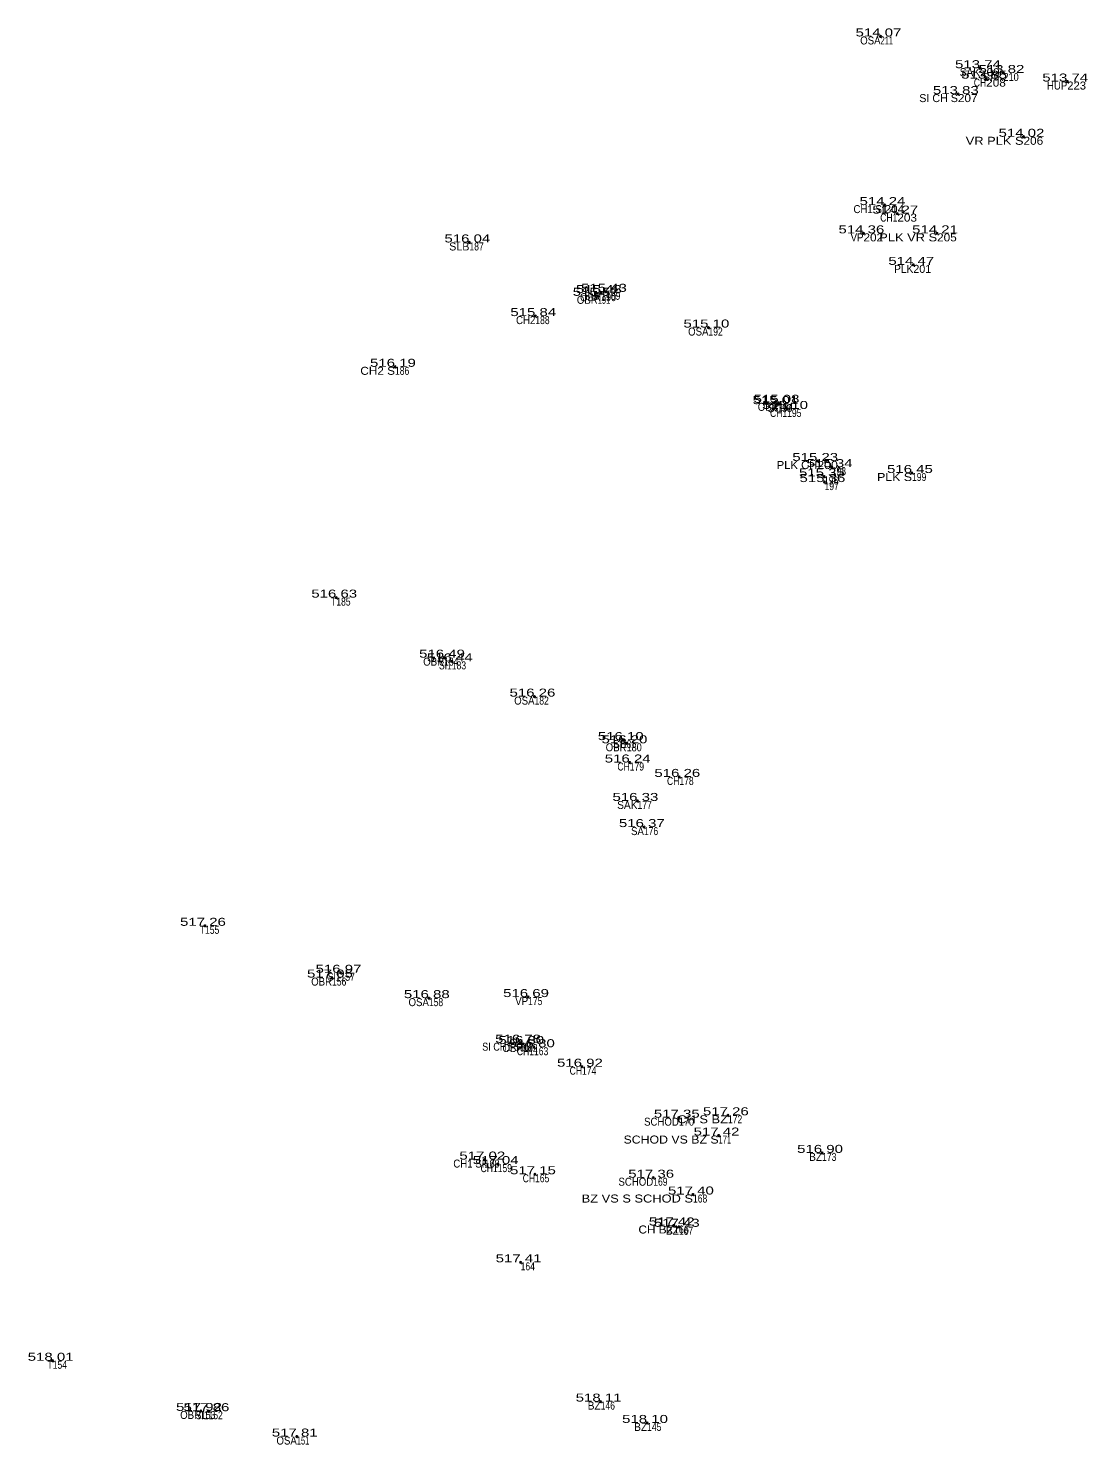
# Model space of a CAD drawing. Extents: x -643086 to -639283, y -1131805 to -1123269.
# Drawn here: x -641480.8 to -641441.1, y -1126139.9 to -1126086.8 of the extents above; entities that cross this region are included whole.
import ezdxf
from ezdxf.enums import TextEntityAlignment as Align

# ---------------------------------------------------------------- set-up
doc = ezdxf.new("R2010")
doc.units = 0
doc.header["$LTSCALE"] = 0.12
doc.header["$PDMODE"] = 32
doc.header["$PDSIZE"] = 0.06
for name, color, linetype in [('1', 7, 'Continuous'), ('2', 7, 'Continuous'), ('3', 7, 'Continuous'), ('4', 7, 'Continuous')]:
    doc.layers.add(name, color=color, linetype=linetype)

msp = doc.modelspace()

# ---------------------------------------------------------------- linework, layer by layer
at = {"layer": '1'}
for p in [(-641448.87, -1126087.1), (-641445.14, -1126088.29), (-641444.26, -1126088.47), (-641444.91, -1126088.68), (-641441.87, -1126088.79), (-641445.97, -1126089.26), (-641443.51, -1126090.86), (-641448.72, -1126093.42), (-641448.24, -1126093.74), (-641464.28, -1126094.82), (-641449.51, -1126094.48), (-641446.75, -1126094.48), (-641447.64, -1126095.66), (-641459.47, -1126096.82), (-641459.35, -1126096.72), (-641459.16, -1126096.67), (-641461.81, -1126097.58), (-641455.32, -1126098.01), (-641467.07, -1126099.48), (-641452.69, -1126100.83), (-641452.73, -1126100.88), (-641452.37, -1126101.06), (-641451.24, -1126103.01), (-641450.7, -1126103.24), (-641447.69, -1126103.46), (-641450.99, -1126103.59), (-641450.97, -1126103.8), (-641469.27, -1126108.13), (-641465.23, -1126110.38), (-641464.94, -1126110.52), (-641461.84, -1126111.84), (-641458.53, -1126113.47), (-641458.39, -1126113.59), (-641458.27, -1126114.31), (-641456.41, -1126114.85), (-641457.98, -1126115.75), (-641457.74, -1126116.73), (-641474.19, -1126120.43), (-641469.43, -1126122.37), (-641469.11, -1126122.19), (-641462.08, -1126123.1), (-641465.8, -1126123.14), (-641462.38, -1126124.81), (-641462.26, -1126124.86), (-641461.86, -1126124.98), (-641460.06, -1126125.71), (-641456.43, -1126127.62), (-641454.59, -1126127.53), (-641454.94, -1126128.29), (-641451.06, -1126128.94), (-641463.72, -1126129.19), (-641463.22, -1126129.36), (-641461.82, -1126129.74), (-641457.39, -1126129.87), (-641455.9, -1126130.5), (-641456.62, -1126131.66), (-641456.43, -1126131.71), (-641462.36, -1126133.04), (-641479.9, -1126136.73), (-641459.36, -1126138.26), (-641474.34, -1126138.61), (-641474.06, -1126138.62), (-641470.75, -1126139.57), (-641457.62, -1126139.06)]:
    msp.add_point(p, dxfattribs=at)

# ---------------------------------------------------------------- texts
at = {"layer": '2'}
for s, width, p in [('211', 0.7, (-641448.87, -1126087.4)), ('209', 1.1, (-641445.14, -1126088.59)), ('210', 0.85, (-641444.26, -1126088.77)), ('208', 1.1, (-641444.91, -1126088.98)), ('223', 1.05, (-641441.87, -1126089.09)), ('207', 1.1, (-641445.97, -1126089.56)), ('206', 1.1, (-641443.51, -1126091.16)), ('204', 1.1, (-641448.72, -1126093.72)), ('203', 1.1, (-641448.24, -1126094.04)), ('187', 0.8, (-641464.28, -1126095.12)), ('202', 1.1, (-641449.51, -1126094.78)), ('205', 1.1, (-641446.75, -1126094.78)), ('191', 0.7, (-641459.47, -1126097.12)), ('190', 0.85, (-641459.35, -1126097.02)), ('189', 0.8, (-641459.16, -1126096.97)), ('188', 0.8, (-641461.81, -1126097.88)), ('192', 0.8, (-641455.32, -1126098.31)), ('186', 0.8, (-641467.07, -1126099.78)), ('193', 0.8, (-641452.73, -1126101.18)), ('194', 0.8, (-641452.69, -1126101.13)), ('195', 0.8, (-641452.37, -1126101.36)), ('200', 1.15, (-641451.24, -1126103.31)), ('198', 0.8, (-641450.7, -1126103.54)), ('199', 0.8, (-641447.69, -1126103.76)), ('196', 0.8, (-641450.99, -1126103.89)), ('197', 0.8, (-641450.97, -1126104.1)), ('185', 0.8, (-641469.27, -1126108.43)), ('184', 0.8, (-641465.23, -1126110.68)), ('183', 0.8, (-641464.94, -1126110.82)), ('182', 0.8, (-641461.84, -1126112.14)), ('181', 0.7, (-641458.53, -1126113.77)), ('180', 0.85, (-641458.39, -1126113.89)), ('179', 0.8, (-641458.27, -1126114.61)), ('178', 0.8, (-641456.41, -1126115.15)), ('177', 0.8, (-641457.98, -1126116.05)), ('176', 0.8, (-641457.74, -1126117.03)), ('155', 0.8, (-641474.19, -1126120.73)), ('156', 0.8, (-641469.43, -1126122.67)), ('157', 0.8, (-641469.11, -1126122.49)), ('175', 0.8, (-641462.08, -1126123.4)), ('158', 0.8, (-641465.8, -1126123.44)), ('161', 0.7, (-641462.38, -1126125.11)), ('162', 0.8, (-641462.26, -1126125.16)), ('163', 0.8, (-641461.86, -1126125.28)), ('174', 0.8, (-641460.06, -1126126.01)), ('170', 0.85, (-641456.43, -1126127.92)), ('172', 0.8, (-641454.59, -1126127.83)), ('171', 0.7, (-641454.94, -1126128.59)), ('173', 0.8, (-641451.06, -1126129.24)), ('160', 0.85, (-641463.72, -1126129.49)), ('159', 0.8, (-641463.22, -1126129.66)), ('165', 0.8, (-641461.82, -1126130.04)), ('169', 0.8, (-641457.39, -1126130.17)), ('168', 0.8, (-641455.9, -1126130.8)), ('166', 0.85, (-641456.62, -1126131.96)), ('167', 0.8, (-641456.43, -1126132.01)), ('164', 0.8, (-641462.36, -1126133.34)), ('154', 0.8, (-641479.9, -1126137.03)), ('146', 0.8, (-641459.36, -1126138.56)), ('153', 0.8, (-641474.34, -1126138.91)), ('152', 0.8, (-641474.06, -1126138.92)), ('145', 0.8, (-641457.62, -1126139.36)), ('151', 0.7, (-641470.75, -1126139.87))]:
    msp.add_text(s, height=0.3, dxfattribs=dict(at, width=width)).set_placement(p)
msp.add_text('201', height=0.3, dxfattribs=at).set_placement((-641447.64, -1126095.96))
at = {"layer": '3', "width": 1.4}
for s, p in [('514 07 ', (-641448.87, -1126087.1)), ('513 74 ', (-641445.14, -1126088.29)), ('513 85 ', (-641444.91, -1126088.68)), ('513 82 ', (-641444.26, -1126088.47)), ('513 74 ', (-641441.87, -1126088.79)), ('513 83 ', (-641445.97, -1126089.26)), ('514 02 ', (-641443.51, -1126090.86)), ('514 24 ', (-641448.72, -1126093.42)), ('514 27 ', (-641448.24, -1126093.74)), ('514 36 ', (-641449.51, -1126094.48)), ('514 21 ', (-641446.75, -1126094.48)), ('516 04 ', (-641464.28, -1126094.82)), ('514 47 ', (-641447.64, -1126095.66)), ('515 52 ', (-641459.47, -1126096.82)), ('515 48 ', (-641459.35, -1126096.72)), ('515 43 ', (-641459.16, -1126096.67)), ('515 84 ', (-641461.81, -1126097.58)), ('515 10 ', (-641455.32, -1126098.01)), ('516 19 ', (-641467.07, -1126099.48)), ('515 01 ', (-641452.73, -1126100.88)), ('515 08 ', (-641452.69, -1126100.83)), ('515 10 ', (-641452.37, -1126101.06)), ('515 23 ', (-641451.24, -1126103.01)), ('515 35 ', (-641450.99, -1126103.59)), ('515 34 ', (-641450.7, -1126103.24)), ('516 45 ', (-641447.69, -1126103.46)), ('515 36 ', (-641450.97, -1126103.8)), ('516 63 ', (-641469.27, -1126108.13)), ('516 49 ', (-641465.23, -1126110.38)), ('516 44 ', (-641464.94, -1126110.52)), ('516 26 ', (-641461.84, -1126111.84)), ('516 10 ', (-641458.53, -1126113.47)), ('516 20 ', (-641458.39, -1126113.59)), ('516 24 ', (-641458.27, -1126114.31)), ('516 26 ', (-641456.41, -1126114.85)), ('516 33 ', (-641457.98, -1126115.75)), ('516 37 ', (-641457.74, -1126116.73)), ('517 26 ', (-641474.19, -1126120.43)), ('516 97 ', (-641469.11, -1126122.19)), ('517 05 ', (-641469.43, -1126122.37)), ('516 88 ', (-641465.8, -1126123.14)), ('516 69 ', (-641462.08, -1126123.1)), ('516 78 ', (-641462.38, -1126124.81)), ('516 80 ', (-641462.26, -1126124.86)), ('516 80 ', (-641461.86, -1126124.98)), ('516 92 ', (-641460.06, -1126125.71)), ('517 35 ', (-641456.43, -1126127.62)), ('517 26 ', (-641454.59, -1126127.53)), ('517 42 ', (-641454.94, -1126128.29)), ('517 02 ', (-641463.72, -1126129.19)), ('516 90 ', (-641451.06, -1126128.94)), ('517 04 ', (-641463.22, -1126129.36)), ('517 15 ', (-641461.82, -1126129.74)), ('517 36 ', (-641457.39, -1126129.87)), ('517 40 ', (-641455.9, -1126130.5)), ('517 42 ', (-641456.62, -1126131.66)), ('517 43 ', (-641456.43, -1126131.71)), ('517 41 ', (-641462.36, -1126133.04)), ('518 01 ', (-641479.9, -1126136.73)), ('518 11 ', (-641459.36, -1126138.26)), ('517 92 ', (-641474.34, -1126138.61)), ('517 86 ', (-641474.06, -1126138.62)), ('518 10 ', (-641457.62, -1126139.06)), ('517 81 ', (-641470.75, -1126139.57))]:
    msp.add_text(s, height=0.3, dxfattribs=at).set_placement(p, align=Align.CENTER)
at = {"layer": '4'}
for s, width, p in [('OSA', 0.9, (-641448.87, -1126087.4)), ('SAK', 0.95, (-641445.14, -1126088.59)), ('SAK', 0.95, (-641444.26, -1126088.77)), ('CH', 0.8, (-641444.91, -1126088.98)), ('HUP', 0.9, (-641441.87, -1126089.09)), ('VR PLK S', 1.2, (-641443.51, -1126091.16)), ('CH1 SI', 0.9, (-641448.72, -1126093.72)), ('CH1', 0.8, (-641448.24, -1126094.04)), ('VP', 0.9, (-641449.51, -1126094.78)), ('PLK VR S', 1.2, (-641446.75, -1126094.78)), ('PLK', 0.95, (-641447.64, -1126095.96)), ('OBR', 0.9, (-641459.47, -1126097.12)), ('OBR', 0.9, (-641459.35, -1126097.02)), ('SI1', 0.8, (-641459.16, -1126096.97)), ('CH2', 0.9, (-641461.81, -1126097.88)), ('OSA', 0.9, (-641455.32, -1126098.31)), ('CH2 S', 1.1, (-641467.07, -1126099.78)), ('OBR', 0.9, (-641452.69, -1126101.13)), ('CH1', 0.8, (-641452.37, -1126101.36)), ('PLK CH', 1.05, (-641451.24, -1126103.31)), ('PLK S', 1.15, (-641447.69, -1126103.76)), ('T', 0.8, (-641469.27, -1126108.43)), ('OBR', 0.9, (-641465.23, -1126110.68)), ('SI1', 0.8, (-641464.94, -1126110.82)), ('OSA', 0.9, (-641461.84, -1126112.14)), ('OBR', 0.9, (-641458.39, -1126113.89)), ('CH', 0.8, (-641458.27, -1126114.61)), ('CH', 0.8, (-641456.41, -1126115.15)), ('SAK', 0.95, (-641457.98, -1126116.05)), ('SA', 0.9, (-641457.74, -1126117.03)), ('T', 0.8, (-641474.19, -1126120.73)), ('OBR', 0.9, (-641469.43, -1126122.67)), ('SI1', 0.8, (-641469.11, -1126122.49)), ('VP', 0.9, (-641462.08, -1126123.4)), ('OSA', 0.9, (-641465.8, -1126123.44)), ('SI CH1 S', 0.85, (-641462.38, -1126125.11)), ('OBR', 0.9, (-641462.26, -1126125.16)), ('CH1', 0.8, (-641461.86, -1126125.28)), ('CH', 0.8, (-641460.06, -1126126.01)), ('SCHOD', 0.9, (-641456.43, -1126127.92)), ('CH S BZ', 1.2, (-641454.59, -1126127.83)), ('SCHOD VS BZ S', 1.15, (-641454.94, -1126128.59)), ('BZ', 0.95, (-641451.06, -1126129.24)), ('CH1 SI', 0.9, (-641463.72, -1126129.49)), ('CH1', 0.8, (-641463.22, -1126129.66)), ('CH', 0.8, (-641461.82, -1126130.04)), ('SCHOD', 0.9, (-641457.39, -1126130.17)), ('BZ VS S SCHOD S', 1.2, (-641455.9, -1126130.8)), ('CH BZ', 1.1, (-641456.62, -1126131.96)), ('BZ', 0.95, (-641456.43, -1126132.01)), ('T', 0.8, (-641479.9, -1126137.03)), ('BZ', 0.95, (-641459.36, -1126138.56)), ('OBR', 0.9, (-641474.34, -1126138.91)), ('SI1', 0.8, (-641474.06, -1126138.92)), ('BZ', 0.95, (-641457.62, -1126139.36)), ('OSA', 0.9, (-641470.75, -1126139.87))]:
    msp.add_text(s, height=0.3, dxfattribs=dict(at, width=width)).set_placement(p, align=Align.RIGHT)
for s, p in [('SI CH S', (-641445.97, -1126089.56)), ('SLB', (-641464.28, -1126095.12)), ('SI', (-641452.73, -1126101.18)), ('SI', (-641458.53, -1126113.77))]:
    msp.add_text(s, height=0.3, dxfattribs=at).set_placement(p, align=Align.RIGHT)

doc.saveas('drawing.dxf')
